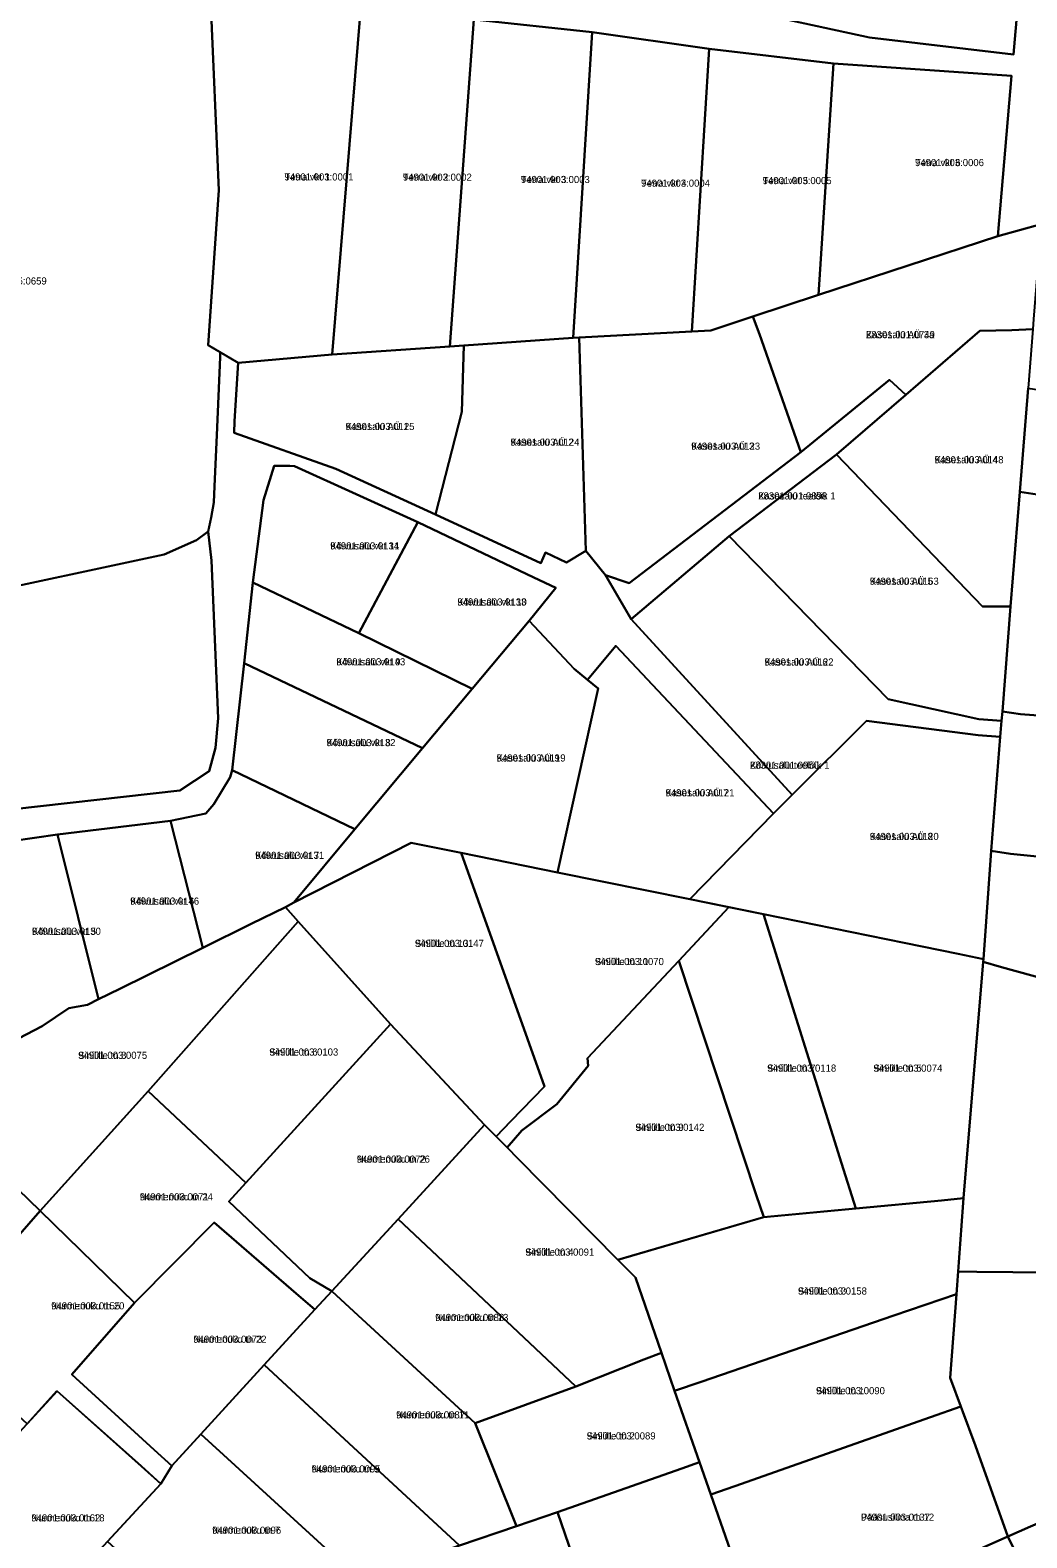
# Model space of a CAD drawing. Extents: x 647845 to 668483, y 6445298 to 6473683.
# Drawn here: x 653103.1 to 653312.8, y 6468125.6 to 6468442.7 of the extents above; entities that cross this region are included whole.
import ezdxf

# ---------------------------------------------------------------- set-up
doc = ezdxf.new("R2010")
doc.units = 0
for name, color, linetype in [('L_AADRESS', 7, 'Continuous'), ('PIIR', 7, 'Continuous'), ('TUNNUS', 7, 'Continuous')]:
    doc.layers.add(name, color=color, linetype=linetype)

msp = doc.modelspace()

# ---------------------------------------------------------------- linework, layer by layer
at = {"layer": 'PIIR'}
for points in [[(653333.23, 6468613.76), (653317.65, 6468423.77), (653315.86, 6468401.88), (653306.73, 6468399.38), (653309.61, 6468433.07), (653272.15, 6468435.7), (653245.98, 6468438.76), (653221.36, 6468442.23), (653196.46, 6468444.93)], [(653260.93, 6468445.19), (653279.74, 6468441.16), (653310.01, 6468437.56), (653312.6, 6468467.38)], [(653400.18, 6468113.08), (653388.98, 6468130.4), (653377.36, 6468150.02), (653374.44, 6468154.13), (653370.16, 6468168.76), (653366.4, 6468181.08), (653363.15, 6468198.86), (653362.17, 6468217.34), (653365.02, 6468263.65), (653369.06, 6468294.6), (653372.42, 6468319.12), (653336.41, 6468335.22), (653315.04, 6468345.02), (653311.36, 6468345.59), (653313.1, 6468367.38), (653316.68, 6468366.82), (653337.82, 6468364.76), (653336.62, 6468338.23), (653374.21, 6468321.52), (653387.35, 6468339.02), (653408.49, 6468363.98), (653428.57, 6468383.73), (653440.81, 6468375.49)], [(653070.29, 6468275.56), (653134.64, 6468282.77), (653140.81, 6468286.82), (653142.15, 6468291.79), (653142.66, 6468298.01), (653141.3, 6468331.13), (653140.59, 6468337.22), (653141.18, 6468340.19), (653141.8, 6468343.37), (653141.94, 6468346.77), (653142.39, 6468357.49), (653143.07, 6468373.88), (653143.13, 6468374.95), (653146.88, 6468372.74), (653146.1, 6468360.49), (653146.02, 6468357.99), (653167.44, 6468350.41), (653188.38, 6468340.8), (653210.57, 6468330.62), (653211.54, 6468332.85), (653215.95, 6468330.75), (653220.02, 6468333.19), (653224.18, 6468328.04), (653229.59, 6468318.84), (653263.43, 6468281.89), (653259.57, 6468277.97), (653226.39, 6468313.22), (653220.43, 6468306.06), (653217.57, 6468308.4), (653208.1, 6468318.5), (653213.73, 6468325.42), (653209.09, 6468327.61), (653184.68, 6468339.22), (653158.76, 6468350.99), (653157.77, 6468351.09), (653154.5, 6468351.07), (653152.24, 6468343.84), (653149.97, 6468326.52), (653148.12, 6468309.55), (653145.64, 6468287.09), (653145.21, 6468285.56), (653141.75, 6468279.9), (653140.09, 6468277.97), (653132.68, 6468276.42), (653108.88, 6468273.5), (653089.47, 6468270.74)], [(653088.65, 6468323.31), (653131.32, 6468332.4), (653138.12, 6468335.41), (653140.59, 6468337.22), (653141.3, 6468331.13), (653142.66, 6468298.01), (653142.15, 6468291.79), (653140.81, 6468286.82), (653134.64, 6468282.77), (653070.29, 6468275.56)]]:
    msp.add_lwpolyline(points, dxfattribs=at)
for points in [[(653279.74, 6468441.16), (653260.93, 6468445.19), (653262.98, 6468471.61), (653312.6, 6468467.38), (653310.01, 6468437.56)], [(653087.15, 6468455.12), (653106.19, 6468452.12), (653126.25, 6468450.45), (653141.05, 6468449.59), (653142.85, 6468409), (653140.61, 6468376.44), (653143.13, 6468374.95), (653143.07, 6468373.88), (653142.39, 6468357.49), (653141.94, 6468346.77), (653141.8, 6468343.37), (653141.18, 6468340.19), (653140.59, 6468337.22), (653138.12, 6468335.41), (653131.32, 6468332.4), (653088.65, 6468323.31), (653051.67, 6468315.43), (653041.08, 6468313.17), (653041.5, 6468317.18), (653045.72, 6468358.09), (653048.9, 6468390.78), (653066.36, 6468392.28), (653067.62, 6468453.16), (653067.74, 6468456.41)], [(653146.88, 6468372.74), (653140.61, 6468376.44), (653142.85, 6468409), (653141.05, 6468449.59), (653172.68, 6468447.5), (653166.64, 6468374.46)], [(653172.68, 6468447.5), (653196.46, 6468444.93), (653191.4, 6468376.17), (653166.64, 6468374.46)], [(653196.46, 6468444.93), (653221.36, 6468442.23), (653217.36, 6468377.95), (653194.36, 6468376.37), (653191.4, 6468376.17)], [(653221.36, 6468442.23), (653245.98, 6468438.76), (653242.37, 6468379.33), (653218.61, 6468378.02), (653217.36, 6468377.95)], [(653245.98, 6468438.76), (653272.15, 6468435.7), (653269.02, 6468387.04), (653255.22, 6468382.49), (653246.32, 6468379.55), (653242.37, 6468379.33)], [(653272.15, 6468435.7), (653309.61, 6468433.07), (653306.73, 6468399.38), (653269.02, 6468387.04)], [(653314.09, 6468379.81), (653309.7, 6468379.61), (653302.98, 6468379.48), (653287.35, 6468365.99), (653283.98, 6468369.15), (653265.27, 6468353.94), (653256.56, 6468378.73), (653255.22, 6468382.49), (653269.02, 6468387.04), (653306.73, 6468399.38), (653315.86, 6468401.88), (653314.26, 6468381.94)], [(653218.61, 6468378.02), (653242.37, 6468379.33), (653246.32, 6468379.55), (653255.22, 6468382.49), (653256.56, 6468378.73), (653265.27, 6468353.94), (653229.2, 6468326.41), (653224.18, 6468328.04), (653220.02, 6468333.19)], [(653302.98, 6468379.48), (653309.7, 6468379.61), (653314.09, 6468379.81), (653313.1, 6468367.38), (653311.36, 6468345.59), (653309.38, 6468321.5), (653303.5, 6468321.5), (653272.78, 6468353.43), (653287.35, 6468365.99)], [(653189.09, 6468343.56), (653193.94, 6468362.44), (653194.36, 6468376.37), (653217.36, 6468377.95), (653218.61, 6468378.02), (653220.02, 6468333.19), (653215.95, 6468330.75), (653211.54, 6468332.85), (653210.57, 6468330.62), (653188.38, 6468340.8)], [(653166.64, 6468374.46), (653191.4, 6468376.17), (653194.36, 6468376.37), (653193.94, 6468362.44), (653189.09, 6468343.56), (653188.38, 6468340.8), (653167.44, 6468350.41), (653146.02, 6468357.99), (653146.1, 6468360.49), (653146.88, 6468372.74)], [(653272.78, 6468353.43), (653250.22, 6468336.24), (653229.59, 6468318.84), (653224.18, 6468328.04), (653229.2, 6468326.41), (653265.27, 6468353.94), (653283.98, 6468369.15), (653287.35, 6468365.99)], [(653250.22, 6468336.24), (653272.78, 6468353.43), (653303.5, 6468321.5), (653309.38, 6468321.5), (653307.69, 6468299.4), (653307.54, 6468297.44), (653302.72, 6468297.82), (653283.7, 6468301.98)], [(653152.24, 6468343.84), (653154.5, 6468351.07), (653157.77, 6468351.09), (653158.76, 6468350.99), (653184.68, 6468339.22), (653172.3, 6468315.87), (653149.97, 6468326.52)], [(653336.41, 6468335.22), (653372.42, 6468319.12), (653369.06, 6468294.6), (653333.11, 6468297.24), (653311.54, 6468298.83), (653307.69, 6468299.4), (653309.38, 6468321.5), (653311.36, 6468345.59), (653315.04, 6468345.02)], [(653209.09, 6468327.61), (653213.73, 6468325.42), (653208.1, 6468318.5), (653196.1, 6468304.14), (653172.3, 6468315.87), (653184.68, 6468339.22)], [(653250.22, 6468336.24), (653283.7, 6468301.98), (653302.72, 6468297.82), (653307.54, 6468297.44), (653307.23, 6468294.07), (653302.59, 6468294.44), (653279.1, 6468297.42), (653263.43, 6468281.89), (653229.59, 6468318.84)], [(653172.3, 6468315.87), (653196.1, 6468304.14), (653185.68, 6468291.68), (653148.12, 6468309.55), (653149.97, 6468326.52)], [(653217.57, 6468308.4), (653220.43, 6468306.06), (653222.63, 6468304.25), (653214.07, 6468265.51), (653193.79, 6468269.65), (653183.28, 6468271.8), (653158.57, 6468259.25), (653171.46, 6468274.66), (653185.68, 6468291.68), (653196.1, 6468304.14), (653208.1, 6468318.5)], [(653226.39, 6468313.22), (653259.57, 6468277.97), (653241.94, 6468259.96), (653214.07, 6468265.51), (653222.63, 6468304.25), (653220.43, 6468306.06)], [(653185.68, 6468291.68), (653171.46, 6468274.66), (653145.64, 6468287.09), (653148.12, 6468309.55)], [(653263.43, 6468281.89), (653279.1, 6468297.42), (653302.59, 6468294.44), (653307.23, 6468294.07), (653305.31, 6468270.08), (653303.71, 6468247.34), (653298.41, 6468248.42), (653241.94, 6468259.96), (653259.57, 6468277.97)], [(653333.11, 6468297.24), (653369.06, 6468294.6), (653365.02, 6468263.65), (653330.28, 6468267.38), (653309.43, 6468269.48), (653305.31, 6468270.08), (653307.23, 6468294.07), (653307.54, 6468297.44), (653307.69, 6468299.4), (653311.54, 6468298.83)], [(653140.09, 6468277.97), (653141.75, 6468279.9), (653145.21, 6468285.56), (653145.64, 6468287.09), (653171.46, 6468274.66), (653158.57, 6468259.25), (653156.84, 6468258.27), (653149.66, 6468254.73), (653139.46, 6468249.71), (653132.68, 6468276.42)], [(653132.68, 6468276.42), (653139.46, 6468249.71), (653121.97, 6468241.09), (653117.53, 6468238.89), (653108.88, 6468273.5)], [(653108.88, 6468273.5), (653117.53, 6468238.89), (653115.2, 6468237.74), (653111.23, 6468236.99), (653105.63, 6468233.25), (653099.07, 6468229.79), (653095.48, 6468245.8), (653089.47, 6468270.74)], [(653201.15, 6468210.05), (653198.72, 6468212.51), (653178.95, 6468233.63), (653159.55, 6468255.25), (653156.84, 6468258.27), (653158.57, 6468259.25), (653183.28, 6468271.8), (653193.79, 6468269.65), (653211.33, 6468220.57), (653204.25, 6468213.25)], [(653214.07, 6468265.51), (653241.94, 6468259.96), (653250.16, 6468258.28), (653239.61, 6468246.99), (653220.4, 6468226.52), (653220.52, 6468224.86), (653213.95, 6468216.79), (653206.56, 6468211.29), (653203.48, 6468207.7), (653201.15, 6468210.05), (653204.25, 6468213.25), (653211.33, 6468220.57), (653193.79, 6468269.65)], [(653330.28, 6468267.38), (653365.02, 6468263.65), (653362.17, 6468217.34), (653334.23, 6468228.47), (653334.52, 6468236.78), (653334.27, 6468239.01), (653331.51, 6468239.8), (653321.07, 6468241.91), (653307.52, 6468245.61), (653303.66, 6468246.76), (653303.71, 6468247.34), (653305.31, 6468270.08), (653309.43, 6468269.48)], [(653159.55, 6468255.25), (653155.18, 6468250.32), (653127.94, 6468219.57), (653105.24, 6468194.42), (653079.36, 6468219.39), (653099.07, 6468229.79), (653105.63, 6468233.25), (653111.23, 6468236.99), (653115.2, 6468237.74), (653117.53, 6468238.89), (653121.97, 6468241.09), (653139.46, 6468249.71), (653149.66, 6468254.73), (653156.84, 6468258.27)], [(653257.48, 6468193.03), (653255.91, 6468197.77), (653239.61, 6468246.99), (653250.16, 6468258.28), (653257.43, 6468256.79), (653273.87, 6468204.42), (653276.86, 6468194.88)], [(653276.86, 6468194.88), (653273.87, 6468204.42), (653257.43, 6468256.79), (653298.41, 6468248.42), (653303.71, 6468247.34), (653303.66, 6468246.76), (653299.5, 6468197.03), (653294.92, 6468196.58)], [(653178.95, 6468233.63), (653175.38, 6468229.72), (653148.51, 6468200.31), (653127.94, 6468219.57), (653155.18, 6468250.32), (653159.55, 6468255.25)], [(653255.91, 6468197.77), (653257.48, 6468193.03), (653226.79, 6468184.09), (653205.8, 6468205.35), (653203.48, 6468207.7), (653206.56, 6468211.29), (653213.95, 6468216.79), (653220.52, 6468224.86), (653220.4, 6468226.52), (653239.61, 6468246.99)], [(653331.51, 6468239.8), (653334.27, 6468239.01), (653334.52, 6468236.78), (653334.23, 6468228.47), (653362.17, 6468217.34), (653363.15, 6468198.86), (653366.4, 6468181.08), (653325.13, 6468181.33), (653302.33, 6468181.54), (653298.37, 6468181.66), (653299.5, 6468197.03), (653303.66, 6468246.76), (653307.52, 6468245.61), (653321.07, 6468241.91)], [(653166.59, 6468177.48), (653162, 6468180.24), (653144.95, 6468196.32), (653148.51, 6468200.31), (653175.38, 6468229.72), (653178.95, 6468233.63), (653198.72, 6468212.51), (653180.53, 6468192.67)], [(653076.39, 6468173.43), (653084.24, 6468182.61), (653056.37, 6468208.06), (653079.36, 6468219.39), (653105.24, 6468194.42), (653082.22, 6468168.12), (653080.11, 6468170.05)], [(653163.04, 6468173.61), (653159.1, 6468177.02), (653141.86, 6468191.94), (653125.06, 6468175.07), (653105.24, 6468194.42), (653127.94, 6468219.57), (653148.51, 6468200.31), (653144.95, 6468196.32), (653162, 6468180.24), (653166.59, 6468177.48)], [(653201.15, 6468210.05), (653203.48, 6468207.7), (653205.8, 6468205.35), (653226.79, 6468184.09), (653230.48, 6468180.35), (653235.99, 6468164.56), (653232.24, 6468163.11), (653217.96, 6468157.42), (653185.21, 6468188.26), (653180.53, 6468192.67), (653198.72, 6468212.51)], [(653238.71, 6468156.52), (653235.99, 6468164.56), (653230.48, 6468180.35), (653226.79, 6468184.09), (653257.41, 6468193.06), (653276.85, 6468194.86), (653294.92, 6468196.58), (653299.5, 6468197.03), (653298.02, 6468176.9), (653284.85, 6468172.36), (653244.33, 6468158.44)], [(653082.22, 6468168.12), (653105.24, 6468194.42), (653125.06, 6468175.07), (653111.91, 6468159.99), (653129.22, 6468144.14), (653132.9, 6468140.76), (653130.64, 6468137.01), (653126.55, 6468140.66), (653108.78, 6468156.49), (653102.5, 6468149.63)], [(653180.53, 6468192.67), (653185.21, 6468188.26), (653217.96, 6468157.42), (653196.77, 6468149.76), (653171.24, 6468173.2), (653166.59, 6468177.48)], [(653152.38, 6468162), (653139.03, 6468147.44), (653132.9, 6468140.76), (653129.22, 6468144.14), (653111.91, 6468159.99), (653125.06, 6468175.07), (653141.86, 6468191.94), (653159.1, 6468177.02), (653163.04, 6468173.61)], [(653302.33, 6468181.54), (653325.13, 6468181.33), (653328.02, 6468181.3), (653330.05, 6468168.95), (653341.68, 6468140.04), (653339.51, 6468139.11), (653334.92, 6468137.13), (653313.65, 6468128.03), (653308.82, 6468125.87), (653302.01, 6468144.98), (653296.72, 6468159.3), (653298.02, 6468176.9), (653298.37, 6468181.66)], [(653163.04, 6468173.61), (653166.59, 6468177.48), (653171.24, 6468173.2), (653196.77, 6468149.76), (653205.46, 6468128.06), (653193.46, 6468123.98), (653157.11, 6468157.62), (653152.38, 6468162)], [(653243.99, 6468141.53), (653238.71, 6468156.52), (653244.33, 6468158.44), (653284.85, 6468172.36), (653298.02, 6468176.9), (653296.72, 6468159.3), (653298.96, 6468153.24), (653292.57, 6468151), (653251.42, 6468136.51), (653246.36, 6468134.73)], [(653238.71, 6468156.52), (653243.99, 6468141.53), (653240.28, 6468140.22), (653214.07, 6468130.99), (653205.46, 6468128.06), (653196.77, 6468149.76), (653217.96, 6468157.42), (653232.24, 6468163.11), (653235.99, 6468164.56)], [(653152.38, 6468162), (653157.11, 6468157.62), (653193.46, 6468123.98), (653172.65, 6468116.73), (653143.79, 6468143.09), (653139.03, 6468147.44)], [(653108.76, 6468156.54), (653126.5, 6468140.67), (653130.64, 6468137.01), (653119.41, 6468124.87), (653097.41, 6468101.09), (653077.36, 6468119.85), (653076.11, 6468121.03), (653078.78, 6468123.92), (653102.5, 6468149.63)], [(653264.38, 6468106.08), (653256.64, 6468105.2), (653246.36, 6468134.73), (653251.42, 6468136.51), (653292.57, 6468151), (653298.96, 6468153.24), (653302.01, 6468144.98), (653308.82, 6468125.87), (653275.11, 6468110.87)], [(653334.92, 6468137.13), (653374.44, 6468154.13), (653377.36, 6468150.02), (653388.98, 6468130.4), (653400.18, 6468113.08), (653357.06, 6468095.35), (653331.09, 6468084.64), (653328.31, 6468083.51), (653324.38, 6468091.38), (653316.88, 6468109.53), (653308.82, 6468125.87), (653313.65, 6468128.03)], [(653130.64, 6468137.01), (653132.9, 6468140.76), (653139.03, 6468147.44), (653143.79, 6468143.09), (653172.65, 6468116.73), (653159.18, 6468112.04), (653140.44, 6468105.51), (653123.58, 6468121.03), (653119.41, 6468124.87)], [(653248.35, 6468104.26), (653226.33, 6468095.4), (653224.41, 6468100.99), (653214.07, 6468130.99), (653240.28, 6468140.22), (653243.99, 6468141.53), (653246.36, 6468134.73), (653256.64, 6468105.2)], [(653198.72, 6468085.65), (653197, 6468090.73), (653186.6, 6468121.59), (653193.46, 6468123.98), (653205.46, 6468128.06), (653214.07, 6468130.99), (653224.41, 6468100.99), (653226.33, 6468095.4), (653222.08, 6468093.71)], [(653276.13, 6468108.26), (653275.11, 6468110.87), (653308.82, 6468125.87), (653316.88, 6468109.53), (653324.38, 6468091.38), (653316.06, 6468088.38), (653292.04, 6468079.71), (653287.95, 6468078.06)]]:
    msp.add_lwpolyline(points, close=True, dxfattribs=at)

# ---------------------------------------------------------------- texts
at = {"layer": 'L_AADRESS'}
for s, p in [('Terra vkt 6', (653289.32, 6468414.09)), ('Terra vkt 1', (653156.64, 6468411.07)), ('Terra vkt 2', (653181.55, 6468411.02)), ('Terra vkt 3', (653206.38, 6468410.53)), ('Terra vkt 5', (653257.26, 6468410.3)), ('Terra vkt 4', (653231.67, 6468409.76)), ('Kasesalu AÜ 3a', (653279, 6468377.91)), ('Kasesalu AÜ 1', (653169.49, 6468358.59)), ('Kasesalu AÜ 2', (653204.2, 6468355.29)), ('Kasesalu AÜ 3', (653242.22, 6468354.45)), ('Kasesalu AÜ 4', (653293.44, 6468351.6)), ('Kasesalu teelõik 1', (653256.32, 6468343.99)), ('Kõivusalu vkt 11', (653166.26, 6468333.48)), ('Kasesalu AÜ 5', (653279.8, 6468326.05)), ('Kõivusalu vkt 10', (653193.03, 6468321.68)), ('Kõivusalu vkt 9', (653167.55, 6468309.1)), ('Kasesalu AÜ 6', (653257.66, 6468309.07)), ('Kõivusalu vkt 8', (653165.49, 6468292.11)), ('Kasesalu AÜ 9', (653201.28, 6468288.88)), ('Kõivusalu teelõik 1', (653254.58, 6468287.36)), ('Kasesalu AÜ 7', (653236.82, 6468281.56)), ('Kasesalu AÜ 8', (653279.8, 6468272.38)), ('Kõivusalu vkt 7', (653150.47, 6468268.4)), ('Kõivusalu vkt 6', (653124.17, 6468258.78)), ('Kõivusalu vkt 5', (653103.5, 6468252.43)), ('Sinilille tn 13', (653184.09, 6468249.89)), ('Sinilille tn 11', (653221.97, 6468246.07)), ('Sinilille tn 8', (653113.24, 6468226.35)), ('Sinilille tn 6', (653153.45, 6468227.04)), ('Sinilille tn 7', (653258.23, 6468223.66)), ('Sinilille tn 5', (653280.57, 6468223.65)), ('Sinilille tn 9', (653230.48, 6468211.21)), ('Nurmenuku tn 26', (653171.84, 6468204.52)), ('Nurmenuku tn 24', (653126.19, 6468196.59)), ('Sinilille tn 4', (653207.32, 6468184.97)), ('Sinilille tn 3', (653264.69, 6468176.78)), ('Nurmenuku tn 20', (653107.56, 6468173.66)), ('Nurmenuku tn 13', (653188.36, 6468171.22)), ('Nurmenuku tn 22', (653137.47, 6468166.64)), ('Sinilille tn 1', (653268.48, 6468155.82)), ('Nurmenuku tn 11', (653180.13, 6468150.73)), ('Sinilille tn 2', (653220.23, 6468146.31)), ('Nurmenuku tn 9', (653162.35, 6468139.37)), ('Nurmenuku tn 18', (653103.38, 6468129.07)), ('Pääsusilma tn 12', (653277.95, 6468129.22)), ('Nurmenuku tn 7', (653141.44, 6468126.48))]:
    msp.add_text(s, height=1.5, dxfattribs=at).set_placement(p)
at = {"layer": 'TUNNUS'}
for s, p in [('94901:003:0006', (653289.32, 6468414.09)), ('94901:003:0001', (653156.64, 6468411.07)), ('94901:003:0002', (653181.55, 6468411.02)), ('94901:003:0003', (653206.38, 6468410.53)), ('94901:003:0005', (653257.26, 6468410.3)), ('94901:003:0004', (653231.67, 6468409.76)), ('94901:005:0659', (653092.11, 6468389.19)), ('28301:001:0749', (653279, 6468377.91)), ('94901:003:0125', (653169.49, 6468358.59)), ('94901:003:0124', (653204.2, 6468355.29)), ('94901:003:0123', (653242.22, 6468354.45)), ('94901:003:0148', (653293.44, 6468351.6)), ('28301:001:0898', (653256.32, 6468343.99)), ('94901:003:0134', (653166.26, 6468333.48)), ('94901:003:0163', (653279.8, 6468326.05)), ('94901:003:0133', (653193.03, 6468321.68)), ('94901:003:0143', (653167.55, 6468309.1)), ('94901:003:0122', (653257.66, 6468309.07)), ('94901:003:0132', (653165.49, 6468292.11)), ('94901:003:0119', (653201.28, 6468288.88)), ('28301:001:0950', (653254.58, 6468287.36)), ('94901:003:0121', (653236.82, 6468281.56)), ('94901:003:0120', (653279.8, 6468272.38)), ('94901:003:0131', (653150.47, 6468268.4)), ('94901:003:0146', (653124.17, 6468258.78)), ('94901:003:0130', (653103.5, 6468252.43)), ('94901:003:0147', (653184.09, 6468249.89)), ('94901:003:0070', (653221.97, 6468246.07)), ('94901:003:0075', (653113.24, 6468226.35)), ('94901:003:0103', (653153.45, 6468227.04)), ('94901:003:0118', (653258.23, 6468223.66)), ('94901:003:0074', (653280.57, 6468223.65)), ('94901:003:0142', (653230.48, 6468211.21)), ('94901:003:0072', (653171.84, 6468204.52)), ('94901:003:0071', (653126.19, 6468196.59)), ('94901:003:0091', (653207.32, 6468184.97)), ('94901:003:0158', (653264.69, 6468176.78)), ('94901:003:0155', (653107.56, 6468173.66)), ('94901:003:0088', (653188.36, 6468171.22)), ('94901:003:0073', (653137.47, 6468166.64)), ('94901:003:0090', (653268.48, 6468155.82)), ('94901:003:0087', (653180.13, 6468150.73)), ('94901:003:0089', (653220.23, 6468146.31)), ('94901:003:0095', (653162.35, 6468139.37)), ('94901:003:0162', (653103.38, 6468129.07)), ('94901:003:0137', (653277.95, 6468129.22)), ('94901:003:0096', (653141.44, 6468126.48))]:
    msp.add_text(s, height=1.5, dxfattribs=at).set_placement(p)

doc.saveas('drawing.dxf')
